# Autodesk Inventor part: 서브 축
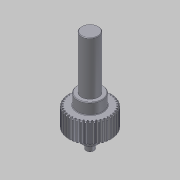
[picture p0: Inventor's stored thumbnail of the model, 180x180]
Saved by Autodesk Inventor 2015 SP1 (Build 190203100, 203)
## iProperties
Created: 2014-07
Part Number: 서브 축
Material: 강
Document SubType Name: Modeling
Designer: KYOUNG IL JANG
Categories: <?xml version="1.0" encoding="UTF-16"?> <MemberInstance><Categories><FamilyTemplate><FamilyTemplateParameter ValueType="xs:double" Id="1" ObjectReferenceKey="da
Density: 1 g/cm^3
Appearance: 강철
CustomPartVersion: 1
Company: 한국ATC센터
Author: KYOUNG IL JANG
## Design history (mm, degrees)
sketch "Sketch1"
  geometry: C1 r 21 at (0, 0)
  constraints: 1 centre point
  dimensions: "d0" = 42 diameter of C1 (= da_da)
extrude "Extrusion1" new body sketch "Sketch1" distance "d1" = 20 (= da_b); taper "d2" = 0 deg
workplane "Work Plane2"
feature "피치 지름" dims "d4" = 10, "d5" = 0
workplane "Work Plane8"
workplane "Work Plane9"
chamfer "모따기1" distance "d49" = 1; stored, may be unused: second distance "d50" = 2, angle "d51" = 45 deg
sketch "스케치3"
  geometry: C1 r 12.5 at (0, 0); 1 further point
  constraints: 1 centre point, 1 coincident
  dimensions: "d52" = 25 diameter of C1
extrude "돌출2" join sketch "스케치3" distance "d53" = 11; taper "d54" = 0 deg
sketch "스케치4"
  geometry: C1 r 8.5 at (0, 0); 1 further point
  constraints: 1 centre point, 1 coincident
  dimensions: "d55" = 17 diameter of C1
extrude "돌출3" join sketch "스케치4" distance "d56" = 53; taper "d57" = 0 deg
sketch "스케치5"
  geometry: C1 r 7.5 at (0, 0); 1 further point
  constraints: 1 centre point, 1 coincident
  dimensions: "d62" = 15 diameter of C1
extrude "돌출4" join sketch "스케치5" distance "d63" = 11; taper "d64" = 0 deg
sketch "스케치6"
  geometry: C1 r 4 at (0, 0); 1 further point
  constraints: 1 centre point, 1 coincident
  dimensions: "d65" = 8 diameter of C1
extrude "돌출5" join sketch "스케치6" distance "d66" = 7; taper "d67" = 0 deg
chamfer "모따기2" distance "d58" = 0.5; stored, may be unused: second distance "d59" = 2, angle "d60" = 45 deg
fillet "모깎기1" dims "d61" = 0.5
feature "스퍼 기어" dims "da_b" = 20, "da_d" = 40, "da_aw" = 31, "da_da" = 42, "da_df" = 37.5, "da_dw" = 40, angle "da_beta" = 0 deg, "da_lefttooth" = 0, "da_righttooth" = 0
body "Solid1"
sketch "Sketch2"
  geometry: C1 r 21 at (0, 0) reference; C2 r 20 at (0, 0)
  constraints: 1 centre point, 1 coincident
  dimensions: "d3" = 40 diameter of C2 (= da_dw)
body "Srf1"
other parameters: "d16" = 31 (= da_aw), "d17" = 0, "d34" = 4.5 deg (computed from da_z), "d39" = 0, "d41" = 0, "d43" = 31 (= da_aw), "d46" = 31 (= da_aw), "d47" = 0, "d48" = 0
